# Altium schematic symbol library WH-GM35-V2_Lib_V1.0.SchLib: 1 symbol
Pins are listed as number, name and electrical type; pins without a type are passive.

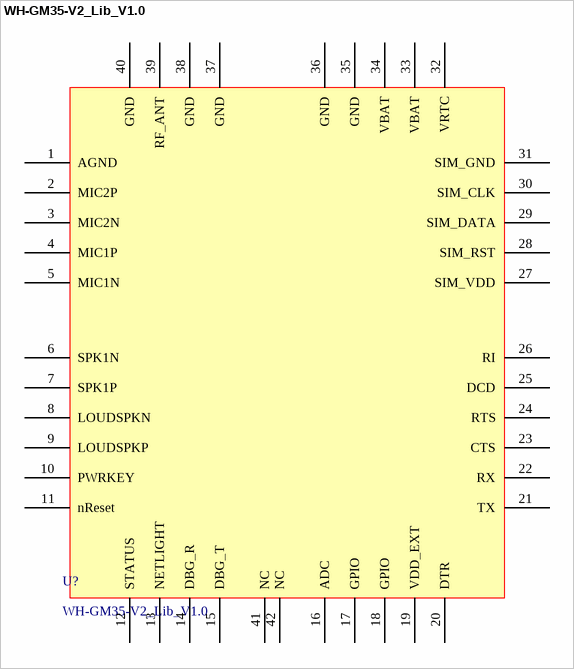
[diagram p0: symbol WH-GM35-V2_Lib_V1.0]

## WH-GM35-V2_Lib_V1.0
designator U?
pins: 1 AGND, 2 MIC2P, 3 MIC2N, 4 MIC1P, 5 MIC1N, 6 SPK1N, 7 SPK1P, 8 LOUDSPKN, 9 LOUDSPKP, 10 PWRKEY, 11 nReset, 12 STATUS, 13 NETLIGHT, 14 DBG_R, 15 DBG_T, 16 ADC, 17 GPIO, 18 GPIO, 19 VDD_EXT, 20 DTR, 21 TX, 22 RX, 23 CTS, 24 RTS, 25 DCD, 26 RI, 27 SIM_VDD, 28 SIM_RST, 29 SIM_DATA, 30 SIM_CLK, 31 SIM_GND, 32 VRTC, 33 VBAT, 34 VBAT, 35 GND, 36 GND, 37 GND, 38 GND, 39 RF_ANT, 40 GND, 41 NC, 42 NC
